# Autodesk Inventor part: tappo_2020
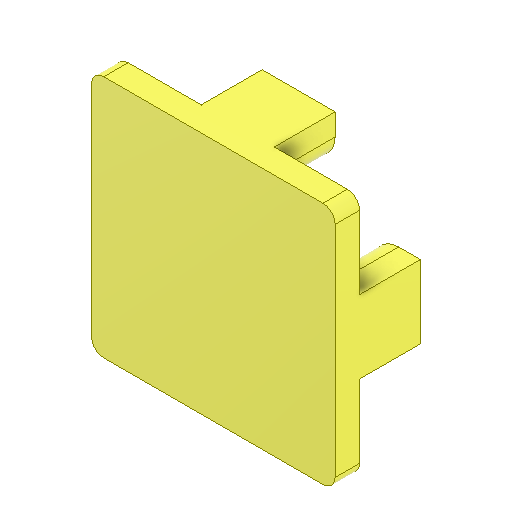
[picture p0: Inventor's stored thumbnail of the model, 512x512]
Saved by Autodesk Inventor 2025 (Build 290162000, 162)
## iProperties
Created: 2025-09
Part Number: tappo_2020
Material: Plastica ABS
Document SubType Name: Modeling
Designer: Ryzen5700u
Density: 1.06 g/cm^3
Appearance: Liscia - Giallo
Author: Ryzen5700u
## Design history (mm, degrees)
sketch "Schizzo1"
  geometry: L1 (-10, 10)-(10, 10); L2 (10, 10)-(10, -10); L3 (10, -10)-(-10, -10); L4 (-10, -10)-(-10, 10); L5 (-10, 10)-(10, -10); L6 (10, 10)-(-10, -10); 1 further point
  constraints: 12 end point, 2 midpoint, 2 parallel, 1 horizontal, 1 perpendicular
  dimensions: "d0" = 20 distance of L2.end L3.end; "d1" = 20 distance of L1.end L2.end
extrude "Estrusione1" new body sketch "Schizzo1" distance "d2" = 2; taper "d3" = 0 deg
sketch "Schizzo2"
  geometry: L1 (10, -10)-(-10, -10) reference; L2 (10, 10)-(10, -10) reference; L3 (-10, 10)-(10, 10) reference; L4 (-10, -10)-(-10, 10) reference; L5 (8, 3)-(9.7, 3) reference; L6 (9.7, -3)-(8, -3) reference; L7 (10, -3)-(6.213, -3); L8 (6.213, -3)-(6.213, 3); L9 (6.213, 3)-(10, 3); L10 (10, 3)-(10, -3); 6 further points
  constraints: 8 end point, 2 parallel, 1 horizontal, 1 perpendicular, 1 point on line
extrude "Estrusione2" join sketch "Schizzo2" distance "d4" = 5; taper "d5" = 0 deg
fillet "Raccordo1" dims "d6" = 2
pattern_circular "Serie circolare1" dims "d8" = 360 deg
fillet "Raccordo2" dims "d10" = 1
node "Solido1"
node "Linea chiusa proiettata1"
node "Riferimento1"
node "Riferimento2"
